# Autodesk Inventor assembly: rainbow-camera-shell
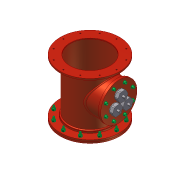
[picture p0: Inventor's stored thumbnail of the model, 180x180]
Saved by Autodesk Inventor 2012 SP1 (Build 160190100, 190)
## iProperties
Created: 2012-02
Part Number: rainbow-camera-shell
Document SubType Name: Assembly
Designer: LACO
Mass: 5159.18 g
Surface Area: 6769.96 cm^2
Volume: 1950.25 cm^3
Density: 2.64539 g/cm^3
Author: LACO
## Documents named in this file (15)
- C:\Documents and Settings\LACO\My Documents\Inventor\rainbow-camera-mount\01 assemblies\rainbow-camera-shell.iam
- C:\Documents and Settings\LACO\My Documents\Inventor\rainbow-camera-mount\02 parts\1502.ipt
- C:\Documents and Settings\LACO\My Documents\Inventor\rainbow-camera-mount\02 parts\1501.iam
- C:\Documents and Settings\LACO\My Documents\Inventor\rainbow-camera-mount\02 parts\1514.ipt
- C:\Documents and Settings\LACO\My Documents\Inventor\rainbow-camera-mount\02 parts\1515.ipt
- C:\Documents and Settings\LACO\My Documents\Inventor\rainbow-camera-mount\02 parts\8333T31.ipt
- C:\Documents and Settings\LACO\My Documents\Inventor\rainbow-camera-mount\02 parts\97775A260.ipt
- C:\Documents and Settings\LACO\My Documents\Inventor\rainbow-camera-mount\02 parts\92200A347.ipt
- C:\Documents and Settings\LACO\My Documents\Inventor\rainbow-camera-mount\02 parts\96551A790.ipt
- C:\Documents and Settings\LACO\My Documents\Inventor\rainbow-camera-mount\02 parts\92200A542.ipt
- C:\Documents and Settings\LACO\My Documents\Inventor\rainbow-camera-mount\02 parts\9396K232.ipt
- C:\Documents and Settings\LACO\My Documents\Inventor\rainbow-camera-mount\02 parts\92200A539.ipt
- C:\Documents and Settings\LACO\My Documents\Inventor\rainbow-camera-mount\06 imports\PAVE\pave_feethrough_ieee_mock.ipt
- C:\Documents and Settings\LACO\My Documents\Inventor\rainbow-camera-mount\02 parts\91831A029.ipt
- C:\Documents and Settings\LACO\My Documents\Inventor\rainbow-camera-mount\02 parts\9396K235.ipt
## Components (78 placed, 14 different names)
1. 1502:1 — Mate:13, Mate:18, Mate:19, Mate:23, Tangent:1, Insert:1, Mate:25, Insert:2, Insert:3, Insert:4, Insert:5, Insert:6, Insert:7, Insert:8, Insert:9, Insert:18, Insert:19, Insert:20, Insert:21, Insert:22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
2. 1501:1 [sub-assembly] — Mate:13, Mate:18, Mate:19, Mate:20, Mate:21, Mate:22, Insert:61, Insert:62, Insert:63, Insert:64, Insert:65, Insert:66, Insert:67, Insert:68, Insert:69, Insert:70, Insert:71, Insert:72, Mate:28
3. 1515:1 — Mate:20, Mate:21, Mate:22, Insert:42, Insert:43, Insert:44, Insert:45, Insert:46, Insert:47, Insert:48, Insert:49, Mate:26, Tangent:2, Insert:58, Insert:59, Insert:60, Mate:28
4. 8333T31:1 — Mate:23, Tangent:1
5. 9396K232:1 — Mate:26, Tangent:2
6. 1514:1 — Insert:1, Mate:25
7. pave_feethrough_ieee_mock:1 — Insert:58
8. pave_feethrough_ieee_mock:2 — Insert:59
9. pave_feethrough_ieee_mock:3 — Insert:60
10. 9396K235:1 — Tangent:3, Mate:27
11. 97775A260:1 — Insert:2, Insert:10
12. 97775A260:2 — Insert:3, Insert:11
13. 97775A260:3 — Insert:4, Insert:12
14. 97775A260:4 — Insert:5, Insert:13
15. 97775A260:5 — Insert:6, Insert:14
16. 97775A260:6 — Insert:7, Insert:15
17. 97775A260:7 — Insert:8, Insert:16
18. 97775A260:8 — Insert:9, Insert:17
19. 92200A347:1 — Insert:10
20. 92200A347:2 — Insert:11
21. 92200A347:3 — Insert:12
22. 92200A347:4 — Insert:13
23. 92200A347:5 — Insert:14
24. 92200A347:6 — Insert:15
25. 92200A347:7 — Insert:16
26. 92200A347:8 — Insert:17
27. 91831A029:1 — Insert:61
28. 91831A029:2 — Insert:62
29. 91831A029:3 — Insert:63
30. 91831A029:4 — Insert:64
31. 91831A029:5 — Insert:65
32. 91831A029:6 — Insert:66
33. 91831A029:7 — Insert:67
34. 91831A029:8 — Insert:68
35. 91831A029:9 — Insert:69
36. 91831A029:10 — Insert:70
37. 91831A029:11 — Insert:71
38. 91831A029:12 — Insert:72
39. 96551A790:1 — Insert:18
40. 96551A790:2 — Insert:19
41. 96551A790:3 — Insert:20
42. 96551A790:4 — Insert:21
43. 96551A790:5 — Insert:22
44. 96551A790:6 — Insert:23
45. 96551A790:7 — Insert:24
46. 96551A790:8 — Insert:25
47. 96551A790:9 — Insert:26
48. 96551A790:10 — Insert:27
49. 96551A790:11 — Insert:28
50. 96551A790:12 — Insert:29
51. 92200A542:13
52. 92200A542:14
53. 92200A542:15
54. 92200A542:16
55. 92200A542:17
56. 92200A542:18
57. 92200A542:19
58. 92200A542:20
59. 92200A542:21
60. 92200A542:22
61. 92200A542:23
62. 92200A542:24
63. 92200A539:1 — Insert:50
64. 92200A539:2 — Insert:51
65. 92200A539:3 — Insert:52
66. 92200A539:4 — Insert:53
67. 92200A539:5 — Insert:54
68. 92200A539:6 — Insert:55
69. 92200A539:7 — Insert:56
70. 92200A539:8 — Insert:57
71. 96551A790:13 — Insert:42, Insert:50
72. 96551A790:14 — Insert:43, Insert:51
73. 96551A790:15 — Insert:44, Insert:52
74. 96551A790:16 — Insert:45, Insert:53
75. 96551A790:17 — Insert:46, Insert:54
76. 96551A790:18 — Insert:47, Insert:55
77. 96551A790:19 — Insert:48, Insert:56
78. 96551A790:20 — Insert:49, Insert:57
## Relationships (74: Insert 60, Mate 11, Tangent 3)
- Mate:13: 1502:1 ↔ 1501:1
- Mate:18: 1502:1 ↔ 1501:1
- Mate:19: 1502:1 ↔ 1501:1
- Mate:20: 1501:1 ↔ 1515:1
- Mate:21: 1501:1 ↔ 1515:1
- Mate:22: 1501:1 ↔ 1515:1
- Mate:23: 1502:1 ↔ 8333T31:1
- Tangent:1: 1502:1 ↔ 8333T31:1
- Insert:1: 1502:1 ↔ 1514:1
- Mate:25: 1502:1 ↔ 1514:1
- Insert:2: 1502:1 ↔ 97775A260:1
- Insert:3: 1502:1 ↔ 97775A260:2
- Insert:4: 1502:1 ↔ 97775A260:3
- Insert:5: 1502:1 ↔ 97775A260:4
- Insert:6: 1502:1 ↔ 97775A260:5
- Insert:7: 1502:1 ↔ 97775A260:6
- Insert:8: 1502:1 ↔ 97775A260:7
- Insert:9: 1502:1 ↔ 97775A260:8
- Insert:10: 97775A260:1 ↔ 92200A347:1
- Insert:11: 97775A260:2 ↔ 92200A347:2
- Insert:12: 97775A260:3 ↔ 92200A347:3
- Insert:13: 97775A260:4 ↔ 92200A347:4
- Insert:14: 97775A260:5 ↔ 92200A347:5
- Insert:15: 97775A260:6 ↔ 92200A347:6
- Insert:16: 97775A260:7 ↔ 92200A347:7
- Insert:17: 97775A260:8 ↔ 92200A347:8
- Insert:18: 1502:1 ↔ 96551A790:1
- Insert:19: 1502:1 ↔ 96551A790:2
- Insert:20: 1502:1 ↔ 96551A790:3
- Insert:21: 1502:1 ↔ 96551A790:4
- Insert:22: 1502:1 ↔ 96551A790:5
- Insert:23: 1502:1 ↔ 96551A790:6
- Insert:24: 1502:1 ↔ 96551A790:7
- Insert:25: 1502:1 ↔ 96551A790:8
- Insert:26: 1502:1 ↔ 96551A790:9
- Insert:27: 1502:1 ↔ 96551A790:10
- Insert:28: 1502:1 ↔ 96551A790:11
- Insert:29: 1502:1 ↔ 96551A790:12
- Insert:42: 1515:1 ↔ 96551A790:13
- Insert:43: 1515:1 ↔ 96551A790:14
- Insert:44: 1515:1 ↔ 96551A790:15
- Insert:45: 1515:1 ↔ 96551A790:16
- Insert:46: 1515:1 ↔ 96551A790:17
- Insert:47: 1515:1 ↔ 96551A790:18
- Insert:48: 1515:1 ↔ 96551A790:19
- Insert:49: 1515:1 ↔ 96551A790:20
- Mate:26: 1515:1 ↔ 9396K232:1
- Tangent:2: 1515:1 ↔ 9396K232:1
- Insert:50: 92200A539:1 ↔ 96551A790:13
- Insert:51: 92200A539:2 ↔ 96551A790:14
- Insert:52: 92200A539:3 ↔ 96551A790:15
- Insert:53: 92200A539:4 ↔ 96551A790:16
- Insert:54: 92200A539:5 ↔ 96551A790:17
- Insert:55: 92200A539:6 ↔ 96551A790:18
- Insert:56: 92200A539:7 ↔ 96551A790:19
- Insert:57: 92200A539:8 ↔ 96551A790:20
- Insert:58: 1515:1 ↔ pave_feethrough_ieee_mock:1
- Insert:59: 1515:1 ↔ pave_feethrough_ieee_mock:2
- Insert:60: 1515:1 ↔ pave_feethrough_ieee_mock:3
- Insert:61: 1501:1 ↔ 91831A029:1
- Insert:62: 1501:1 ↔ 91831A029:2
- Insert:63: 1501:1 ↔ 91831A029:3
- Insert:64: 1501:1 ↔ 91831A029:4
- Insert:65: 1501:1 ↔ 91831A029:5
- Insert:66: 1501:1 ↔ 91831A029:6
- Insert:67: 1501:1 ↔ 91831A029:7
- Insert:68: 1501:1 ↔ 91831A029:8
- Insert:69: 1501:1 ↔ 91831A029:9
- Insert:70: 1501:1 ↔ 91831A029:10
- Insert:71: 1501:1 ↔ 91831A029:11
- Insert:72: 1501:1 ↔ 91831A029:12
- Tangent:3: 1502:1 ↔ 9396K235:1
- Mate:27: 1502:1 ↔ 9396K235:1
- Mate:28: 1501:1 ↔ 1515:1
## Named parameters: sa_0 = 20670 mm
